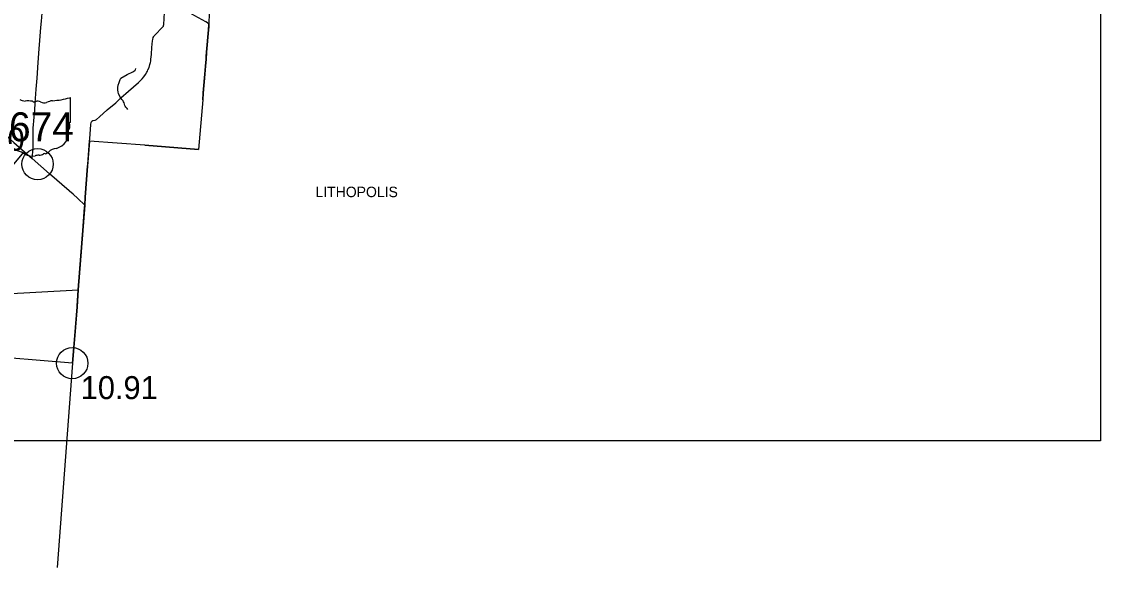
# Model space of a CAD drawing. Extents: x 1659811 to 1934326, y 644115 to 934867.
# Drawn here: x 1874937 to 1926541, y 644115 to 670227 of the extents above; entities that cross this region are included whole.
import ezdxf

# ---------------------------------------------------------------- set-up
doc = ezdxf.new("R2010")
doc.units = 0
for name, color, linetype in [('Default', 7, 'Continuous'), ('GM_X_Adjacent_County', 7, 'Continuous'), ('GM_X_City_Street', 7, 'Continuous'), ('GM_X_Corporation_Text', 7, 'Continuous'), ('GM_X_County', 7, 'Continuous'), ('GM_X_County_Road', 7, 'Continuous'), ('GM_X_State_Route', 7, 'Continuous'), ('GM_X_State_Shield', 7, 'Continuous'), ('SC_Scratch1', 7, 'Continuous')]:
    doc.layers.add(name, color=color, linetype=linetype)

msp = doc.modelspace()

# ---------------------------------------------------------------- linework, layer by layer
at = {"layer": 'Default'}
for centre in [(1875702, 663407), (1877360, 653884), (1877360, 653884)]:
    msp.add_circle(centre, 750, dxfattribs=at)
at = {"layer": 'GM_X_Adjacent_County'}
msp.add_line((1877380, 653885), (1876647, 644115), dxfattribs=at)
at = {"layer": 'GM_X_City_Street'}
for points in [[(1881731, 670044), (1881735, 670079), (1881771, 670662), (1881782, 670836)], [(1883894, 670037), (1883896, 670058), (1883888, 670099), (1883869, 670135), (1883853, 670151), (1883835, 670162), (1883752, 670214), (1883226, 670506), (1882663, 670822)], [(1881348, 669611), (1881646, 669921), (1881701, 669978), (1881719, 670005), (1881731, 670037), (1881731, 670044)], [(1883769, 668549), (1883785, 668758), (1883877, 669831), (1883885, 669930)], [(1883885, 669930), (1883889, 669973), (1883894, 670037)], [(1881145, 668651), (1881147, 668666), (1881173, 668984), (1881198, 669299), (1881209, 669374), (1881237, 669461), (1881257, 669507), (1881280, 669540), (1881332, 669595), (1881348, 669611)], [(1879528, 666423), (1879681, 666578), (1880056, 666902), (1880526, 667316), (1880702, 667494), (1880788, 667591), (1880858, 667689), (1880932, 667807), (1880953, 667852), (1880982, 667913), (1881037, 668037), (1881080, 668176), (1881101, 668265), (1881115, 668338), (1881127, 668434), (1881145, 668651)], [(1883625, 666796), (1883626, 666816), (1883700, 667709), (1883733, 668091), (1883760, 668427), (1883769, 668549)], [(1879681, 666578), (1879644, 666635), (1879568, 666794), (1879555, 666847), (1879539, 666955), (1879534, 667075), (1879554, 667192), (1879604, 667319), (1879651, 667452), (1879661, 667491), (1879679, 667520), (1879988, 667688), (1880254, 667824), (1880350, 667881), (1880386, 667925), (1880409, 667977)], [(1883609, 666477), (1883625, 666796)], [(1878198, 664617), (1878254, 665297), (1878264, 665398), (1878277, 665438), (1878302, 665465), (1878350, 665488), (1878454, 665511), (1878519, 665540), (1878671, 665663), (1879039, 666006), (1879444, 666338), (1879528, 666423)], [(1880026, 666017), (1879983, 666072), (1879930, 666129), (1879894, 666177), (1879876, 666218), (1879857, 666268), (1879837, 666336), (1879814, 666389), (1879790, 666441), (1879740, 666498), (1879681, 666578)], [(1873723, 665190), (1874117, 664838), (1874566, 664446), (1875071, 663996), (1875446, 663673)], [(1878103, 663403), (1878189, 664504), (1878198, 664617)], [(1880829, 664311), (1883392, 664110)], [(1873562, 662223), (1873575, 662245), (1874988, 663903), (1875071, 663996)], [(1877958, 661450), (1877984, 661828), (1878096, 663311), (1878103, 663403)]]:
    msp.add_lwpolyline(points, dxfattribs=at)
at = {"layer": 'GM_X_County'}
msp.add_lwpolyline([(1883910, 670644), (1883888, 670099), (1883896, 670058), (1883889, 669973), (1883877, 669831), (1883785, 668758), (1883760, 668427), (1883733, 668091), (1883700, 667709), (1883625, 666796), (1883609, 666477), (1883392, 664110), (1880829, 664311), (1878189, 664504), (1878096, 663311), (1877984, 661828), (1877958, 661450), (1877649, 657393), (1877591, 656580), (1877433, 654641), (1877380, 653888), (1872712, 654264)], dxfattribs=at)
at = {"layer": 'GM_X_County_Road'}
msp.add_lwpolyline([(1872202, 656780), (1872465, 656982), (1872570, 657045), (1872667, 657091), (1872757, 657116), (1872975, 657143), (1874171, 657208), (1875618, 657288), (1877649, 657393)], dxfattribs=at)
at = {"layer": 'GM_X_State_Route'}
for points in [[(1875487, 664672), (1875486, 664715), (1875485, 664901), (1875488, 664990), (1875492, 665060), (1875497, 665142), (1875510, 665281), (1875529, 665471), (1875569, 665993), (1875591, 666316), (1875642, 666989), (1875675, 667514), (1875726, 668267), (1875776, 668925), (1875808, 669315), (1875858, 669948), (1875886, 670245), (1875919, 670627), (1875980, 671283), (1875989, 671409), (1876033, 671862)], [(1875475, 663988), (1875476, 663991), (1875485, 664137), (1875492, 664285), (1875493, 664406), (1875487, 664672)], [(1875446, 663673), (1875446, 663673), (1875475, 663988)], [(1877958, 661450), (1877635, 661761), (1877411, 661966), (1877232, 662119), (1877219, 662130), (1876275, 662947), (1875446, 663673)], [(1877880, 660436), (1877949, 661344)], [(1877949, 661344), (1877958, 661450)], [(1877593, 656608), (1877649, 657393), (1877880, 660436)], [(1877478, 655196), (1877591, 656580), (1877593, 656608)], [(1877380, 653888), (1877433, 654641), (1877478, 655196)]]:
    msp.add_lwpolyline(points, dxfattribs=at)
at = {"layer": 'GM_X_State_Shield'}
for p, q in [((1877283, 665441), (1877283, 666547)), ((1877282, 665441), (1877283, 665441))]:
    msp.add_line(p, q, dxfattribs=at)
for centre, major_axis, start_param, end_param in [((1875098, 666740), (391, 0), 4.042523, 4.731795), ((1875228, 665308), (1404, 0), 1.404758, 1.657858), ((1875547, 666473), (113, 0), 3.836095, 5.185415), ((1875712, 666229), (235, 0), 0.950623, 2.079405), ((1876015, 666564), (282, 0), 4.081561, 5.145723), ((1876514, 665849), (743, 0), 1.699011, 2.107814), ((1876043, 669375), (3691, 0), 4.814394, 5.042369), ((1877244, 666551), (38.7, 0), 6.141152, 7.989035), ((1877274, 665360), (60, 0), 1.883978, 3.671073), ((1876892, 665220), (360, 0), 5.934695, 6.695948), ((1877241, 665437), (41.5, 0), 5.05454, 6.418171), ((1876250, 664838), (923, 0), 5.101752, 6.440018), ((1877421, 664979), (262, 0), 2.387724, 3.262537), ((1876639, 663751), (506, 0), 1.647645, 2.488434), ((1874531, 663395), (834, 0), 0.823519, 1.323587), ((1875433, 664212), (529, 0), 4.026481, 4.996735), ((1875738, 663482), (435, 0), 1.495662, 1.94098), ((1875777, 664054), (282, 0), 4.691044, 5.507374), ((1876032, 663849), (79.4, 0), 1.147584, 2.315152), ((1875998, 664140), (298, 0), 4.937069, 5.64225)]:
    msp.add_ellipse(centre, major_axis=major_axis, ratio=0.8, start_param=start_param, end_param=end_param, dxfattribs=at)
at = {"layer": 'SC_Scratch1'}
msp.add_lwpolyline([(1730291, 784675), (1926541, 784675), (1926541, 650175), (1730291, 650175)], close=True, dxfattribs=at)

# ---------------------------------------------------------------- texts
at = {"layer": 'Default'}
for s, p in [('2.00', (1872218, 664050)), ('10.91', (1877768, 652166))]:
    msp.add_text(s, height=1100, dxfattribs=at).set_placement(p)
at = {"layer": 'GM_X_Corporation_Text'}
msp.add_text('LITHOPOLIS', height=500, rotation=0, dxfattribs=at).set_placement((1888997, 661828))
at = {"layer": 'GM_X_State_Shield'}
msp.add_text('674', height=1392.2, dxfattribs=at).set_placement((1874334, 664494))

doc.saveas('drawing.dxf')
